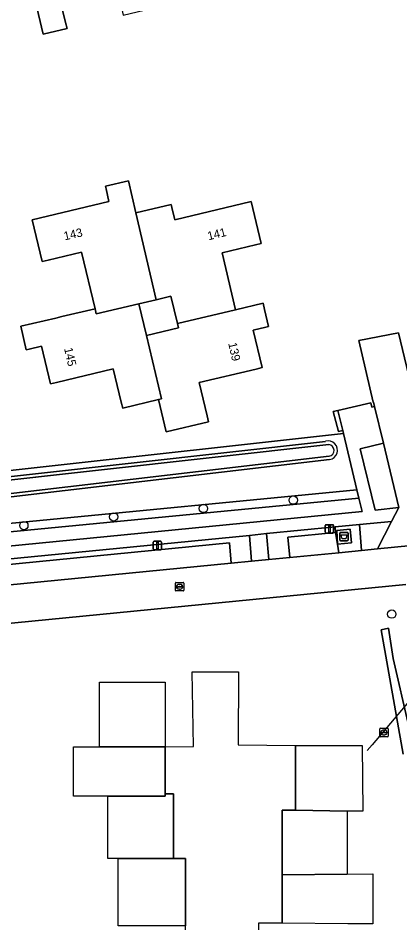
# Model space of a CAD drawing. Extents: x 156661 to 157576, y 383570 to 384425.
# Drawn here: x 156914.8 to 156959.7, y 383880.2 to 383986.9 of the extents above; entities that cross this region are included whole.
import ezdxf

# ---------------------------------------------------------------- set-up
doc = ezdxf.new("R2010")
doc.units = 0
for name, color, linetype in [('IMGEO_Afval_apart_plaats', 7, 'Continuous'), ('IMGEO_Berm_groen', 7, 'Continuous'), ('IMGEO_Boom', 7, 'Continuous'), ('IMGEO_Duiker', 7, 'Continuous'), ('IMGEO_Erf', 7, 'Continuous'), ('IMGEO_Groenvoorziening', 7, 'Continuous'), ('IMGEO_Haag', 7, 'Continuous'), ('IMGEO_Hek', 7, 'Continuous'), ('IMGEO_Lichtmast', 7, 'Continuous'), ('IMGEO_Meer_plas_ven_vijver', 7, 'Continuous'), ('IMGEO_Muur', 7, 'Continuous'), ('IMGEO_Oever', 7, 'Continuous'), ('IMGEO_Pand', 7, 'Continuous'), ('IMGEO_Pand_nummerreeks', 7, 'Continuous'), ('IMGEO_Pand_vergunning_verleend', 7, 'Continuous'), ('IMGEO_Parkeervlak_open', 7, 'Continuous'), ('IMGEO_Rijbaan_lokaal_open', 7, 'Continuous'), ('IMGEO_Rioolput', 7, 'Continuous'), ('IMGEO_Verkeerseiland_groen', 7, 'Continuous'), ('IMGEO_Voetpad_gesloten', 7, 'Continuous'), ('IMGEO_Voetpad_op_trap', 7, 'Continuous'), ('IMGEO_Voetpad_open', 7, 'Continuous'), ('IMGEO_Waterloop', 7, 'Continuous')]:
    doc.layers.add(name, color=color, linetype=linetype)

msp = doc.modelspace()

# ---------------------------------------------------------------- linework, layer by layer
at = {"layer": 'IMGEO_Afval_apart_plaats'}
for p, q in [((156952.64, 383925.35), (156952.64, 383926.15)), ((156952.64, 383926.15), (156952.64, 383925.35)), ((156952.74, 383926.25), (156953.53, 383926.25)), ((156953.53, 383926.25), (156952.74, 383926.25)), ((156953.63, 383926.15), (156953.63, 383925.35)), ((156953.63, 383925.35), (156953.63, 383926.15)), ((156953.53, 383925.25), (156952.74, 383925.25)), ((156952.74, 383925.25), (156953.53, 383925.25))]:
    msp.add_line(p, q, dxfattribs=at)
msp.add_lwpolyline([(156952.79, 383925.96), (156953.49, 383925.96), (156953.34, 383925.49), (156952.94, 383925.49), (156952.79, 383925.96)], dxfattribs=at)
for centre, start, end in [((156952.74, 383926.15), 90, 180), ((156952.74, 383926.15), 90, 180), ((156953.53, 383926.15), 0, 90), ((156953.53, 383926.15), 360, 90), ((156952.74, 383925.35), 180, 270), ((156952.74, 383925.35), 180, 270), ((156953.53, 383925.35), 270, 0), ((156953.53, 383925.35), 270, 0)]:
    msp.add_arc(centre, 0.1, start, end, dxfattribs=at)
at = {"layer": 'IMGEO_Berm_groen'}
msp.add_lwpolyline([(156853.8, 383916.58), (156939.65, 383925.02), (156939.88, 383922.62), (156942.26, 383922.86), (156942.03, 383925.89), (156868.5, 383918.71), (156853.28, 383917.32)], dxfattribs=at)
at = {"layer": 'IMGEO_Boom'}
for centre in [(156947.17, 383930.06), (156936.6, 383929.07), (156926.03, 383928.08), (156915.46, 383927.06), (156958.76, 383916.62)]:
    msp.add_circle(centre, 0.489, dxfattribs=at)
at = {"layer": 'IMGEO_Duiker'}
msp.add_lwpolyline([(156965.05, 383911.36), (156964.87, 383911.15), (156956.47, 383901.23), (156955.88, 383900.53)], dxfattribs=at)
at = {"layer": 'IMGEO_Erf'}
for points in [[(156971.91, 384032.86), (156863.46, 384006.69), (156882.01, 383929.99), (156953.1, 383937.9), (156953.01, 383938.27), (156952.49, 383938.15), (156951.88, 383940.49), (156952.41, 383940.6), (156956.3, 383941.53), (156956.43, 383941), (156956.74, 383941.08), (156956.61, 383941.61), (156956.56, 383941.6), (156954.88, 383948.87), (156959.57, 383949.78), (156961.26, 383942.72)], [(156919.43, 383990.23), (156920.36, 383986.35), (156920.54, 383985.62), (156917.75, 383984.95), (156916.82, 383988.76)]]:
    msp.add_lwpolyline(points, dxfattribs=at)
for points in [[(156932.79, 383964.88), (156932.87, 383964.54), (156933.22, 383963.07), (156942.23, 383965.23), (156943.41, 383960.29), (156942.71, 383960.12), (156938.79, 383959.19), (156940.37, 383952.49), (156943.61, 383953.26), (156943.79, 383952.52), (156944.27, 383950.51), (156943.93, 383950.43), (156942.46, 383950.08), (156943.51, 383945.67), (156942.8, 383945.5), (156936.11, 383943.91), (156937.04, 383939.99), (156937.21, 383939.28), (156932.22, 383938.09), (156931.32, 383941.9), (156927.1, 383940.9), (156926.93, 383941.59), (156925.97, 383945.52), (156919.29, 383943.92), (156918.58, 383943.75), (156917.55, 383948.21), (156916.1, 383947.86), (156915.75, 383947.78), (156915.1, 383950.55), (156919.21, 383951.51), (156919.94, 383951.68), (156923.85, 383952.6), (156922.24, 383959.27), (156918.34, 383958.35), (156917.61, 383958.18), (156916.44, 383963.09), (156925.47, 383965.24), (156925.14, 383966.72), (156925.06, 383967.06), (156927.77, 383967.69), (156928.65, 383963.9)], [(156933.65, 383950.35), (156933.53, 383950.86), (156932.77, 383954.08), (156931.04, 383953.67), (156929, 383953.19), (156929.88, 383949.46)]]:
    msp.add_lwpolyline(points, close=True, dxfattribs=at)
at = {"layer": 'IMGEO_Groenvoorziening'}
for points in [[(156971.83, 384035.57), (156971.46, 384036.85), (156855.45, 384008.78), (156857.54, 383999.9), (156875.12, 383923.56), (156954.67, 383931.28), (156953.1, 383937.9)], [(156953.1, 383937.9), (156882.01, 383929.99), (156863.46, 384006.69), (156971.91, 384032.86), (156984.85, 383993.38), (157001.3, 383943.16), (156963.71, 383939.04), (156964.42, 383936.12), (156965.67, 383936.39)], [(156882.29, 383929.29), (156950.98, 383936.98)], [(156951.45, 383934.84), (156882.83, 383926.78)], [(156960.43, 383920.1), (156912.35, 383915.39), (156904.42, 383914.61), (156868, 383911.04), (156868.44, 383907.02), (156862.51, 383906.39)], [(156960.12, 383900.1), (156957.52, 383914.75), (156958.36, 383914.95), (156958.91, 383911.41), (156960.79, 383903.39), (156961.58, 383900.3)]]:
    msp.add_lwpolyline(points, dxfattribs=at)
for points in [[(156954.9, 383930.3), (156954.67, 383931.28), (156875.12, 383923.56), (156857.54, 383999.9), (156855.45, 384008.78), (156854.96, 384008.66), (156854.48, 384008.54), (156856.57, 383999.67), (156874.23, 383922.97), (156874.34, 383922.48), (156874.83, 383922.53)], [(156957.78, 383936.78), (156955.06, 383936.1), (156956.8, 383928.86), (156959.6, 383929.2)], [(156875.22, 383920.86), (156955.27, 383928.7), (156954.9, 383930.3), (156874.83, 383922.53)], [(156946.77, 383923.3), (156946.52, 383925.7), (156952.13, 383926.24), (156952.09, 383926.89), (156944.03, 383926.11), (156944.3, 383923.06)]]:
    msp.add_lwpolyline(points, close=True, dxfattribs=at)
msp.add_arc((156951.28, 383935.93), 1.1, 278.5005, 105.9803, dxfattribs=at)
at = {"layer": 'IMGEO_Haag'}
msp.add_lwpolyline([(156857.54, 383999.9), (156855.45, 384008.78), (156854.96, 384008.66), (156854.48, 384008.54), (156856.57, 383999.67), (156874.23, 383922.97), (156874.34, 383922.48), (156874.83, 383922.53), (156954.9, 383930.3), (156954.67, 383931.28), (156875.12, 383923.56)], close=True, dxfattribs=at)
at = {"layer": 'IMGEO_Hek'}
msp.add_lwpolyline([(156953.1, 383937.9), (156882.01, 383929.99), (156863.46, 384006.69), (156971.91, 384032.86), (156984.85, 383993.38), (157001.3, 383943.16)], dxfattribs=at)
at = {"layer": 'IMGEO_Lichtmast'}
for p, q in [((156951.03, 383927.16), (156951.82, 383927.16)), ((156951.82, 383927.16), (156951.03, 383927.16)), ((156950.93, 383926.26), (156950.93, 383927.06)), ((156950.93, 383927.06), (156950.93, 383926.26)), ((156951.82, 383926.16), (156951.03, 383926.16)), ((156951.03, 383926.16), (156951.82, 383926.16)), ((156951.92, 383927.06), (156951.92, 383926.26)), ((156951.92, 383926.26), (156951.92, 383927.06)), ((156930.68, 383924.3), (156930.68, 383925.1)), ((156930.68, 383925.1), (156930.68, 383924.3)), ((156930.78, 383925.2), (156931.57, 383925.2)), ((156931.57, 383925.2), (156930.78, 383925.2)), ((156931.67, 383925.1), (156931.67, 383924.3)), ((156931.67, 383924.3), (156931.67, 383925.1)), ((156931.57, 383924.2), (156930.78, 383924.2)), ((156930.78, 383924.2), (156931.57, 383924.2))]:
    msp.add_line(p, q, dxfattribs=at)
for points in [[(156951.35, 383927.03), (156951.5, 383927.03), (156951.5, 383926.28), (156951.35, 383926.28), (156951.35, 383927.03)], [(156931.1, 383925.08), (156931.25, 383925.08), (156931.25, 383924.33), (156931.1, 383924.33), (156931.1, 383925.08)]]:
    msp.add_lwpolyline(points, dxfattribs=at)
for centre, start, end in [((156951.03, 383927.06), 90, 180), ((156951.03, 383927.06), 90, 180), ((156951.82, 383927.06), 0, 90), ((156951.82, 383927.06), 360, 90), ((156951.03, 383926.26), 180, 270), ((156951.03, 383926.26), 180, 270), ((156951.82, 383926.26), 270, 0), ((156951.82, 383926.26), 270, 0), ((156930.78, 383925.1), 90, 180), ((156930.78, 383925.1), 90, 180), ((156931.57, 383925.1), 0, 90), ((156931.57, 383925.1), 360, 90), ((156930.78, 383924.3), 180, 270), ((156930.78, 383924.3), 180, 270), ((156931.57, 383924.3), 270, 0), ((156931.57, 383924.3), 270, 0)]:
    msp.add_arc(centre, 0.1, start, end, dxfattribs=at)
at = {"layer": 'IMGEO_Meer_plas_ven_vijver'}
msp.add_lwpolyline([(156961.58, 383900.3), (156960.79, 383903.39), (156958.91, 383911.41), (156958.36, 383914.95), (156957.52, 383914.75), (156960.12, 383900.1)], dxfattribs=at)
at = {"layer": 'IMGEO_Muur'}
msp.add_lwpolyline([(156956.74, 383941.08), (156956.43, 383941)], dxfattribs=at)
msp.add_lwpolyline([(156952.41, 383940.6), (156951.88, 383940.49), (156952.49, 383938.15), (156953.01, 383938.27)], close=True, dxfattribs=at)
at = {"layer": 'IMGEO_Oever'}
for points in [[(156950.98, 383936.98), (156882.29, 383929.29)], [(156882.3, 383928.89), (156951.36, 383936.62)], [(156951.39, 383935.24), (156882.8, 383927.19)], [(156882.83, 383926.78), (156951.45, 383934.84)]]:
    msp.add_lwpolyline(points, dxfattribs=at)
for centre, radius, start, end in [((156951.28, 383935.93), 1.1, 278.5005, 105.9803), ((156951.28, 383935.92), 0.695, 278.961, 83.5333)]:
    msp.add_arc(centre, radius, start, end, dxfattribs=at)
at = {"layer": 'IMGEO_Pand'}
for points in [[(156918.61, 383997.62), (156918.71, 383997.15), (156914.95, 383996.26), (156916.82, 383988.76), (156917.75, 383984.95), (156920.54, 383985.62), (156920.36, 383986.35), (156919.43, 383990.23), (156926.08, 383991.83), (156926.98, 383987.92), (156927.14, 383987.19), (156932.11, 383988.39), (156929.97, 383997.4), (156931.44, 383997.77), (156931.78, 383997.86), (156931.11, 384000.62), (156930.46, 384000.47), (156929.73, 384000.29), (156925.52, 383999.26)], [(156928.65, 383963.9), (156927.77, 383967.69), (156925.06, 383967.06), (156925.14, 383966.72), (156925.47, 383965.24), (156916.44, 383963.09), (156917.61, 383958.18), (156918.34, 383958.35), (156922.24, 383959.27), (156923.85, 383952.6), (156923.99, 383952.02), (156929, 383953.19), (156931.04, 383953.67)], [(156940.37, 383952.49), (156938.79, 383959.19), (156942.71, 383960.12), (156943.41, 383960.29), (156942.23, 383965.23), (156933.22, 383963.07), (156932.87, 383964.54), (156932.79, 383964.88), (156928.65, 383963.9), (156931.04, 383953.67), (156932.77, 383954.08), (156933.53, 383950.86)], [(156931.32, 383941.9), (156931.66, 383941.98), (156929.88, 383949.46), (156929, 383953.19), (156923.99, 383952.02), (156923.85, 383952.6), (156919.94, 383951.68), (156919.21, 383951.51), (156915.1, 383950.55), (156915.75, 383947.78), (156916.1, 383947.86), (156917.55, 383948.21), (156918.58, 383943.75), (156919.29, 383943.92), (156925.97, 383945.52), (156926.93, 383941.59), (156927.1, 383940.9)], [(156940.37, 383952.49), (156933.53, 383950.86), (156933.65, 383950.35), (156929.88, 383949.46), (156931.66, 383941.98), (156931.32, 383941.9), (156932.22, 383938.09), (156937.21, 383939.28), (156937.04, 383939.99), (156936.11, 383943.91), (156942.8, 383945.5), (156943.51, 383945.67), (156942.46, 383950.08), (156943.93, 383950.43), (156944.27, 383950.51), (156943.79, 383952.52), (156943.61, 383953.26)]]:
    msp.add_lwpolyline(points, close=True, dxfattribs=at)
at = {"layer": 'IMGEO_Pand_vergunning_verleend'}
for points in [[(156947.44, 383901.14), (156947.44, 383893.51), (156945.85, 383893.51), (156945.85, 383885.88), (156945.85, 383880.19), (156943.07, 383880.19), (156943.07, 383874.28), (156934.5, 383874.28), (156934.5, 383879.89), (156934.5, 383887.82), (156933.08, 383887.82), (156933.08, 383895.45), (156932.09, 383895.45), (156932.09, 383901), (156935.41, 383901.03), (156935.26, 383909.8), (156940.71, 383909.8), (156940.68, 383901.21)], [(156932.09, 383908.59), (156932.09, 383901), (156924.36, 383901), (156924.36, 383908.59)], [(156924.36, 383901), (156932.09, 383901), (156932.09, 383895.45), (156932.08, 383895.15), (156925.35, 383895.15), (156921.32, 383895.15), (156921.32, 383901)], [(156953.53, 383893.41), (156947.44, 383893.51), (156947.44, 383901.14), (156955.26, 383901.14), (156955.35, 383893.41)], [(156925.35, 383895.15), (156932.08, 383895.15), (156932.09, 383895.45), (156933.08, 383895.45), (156933.08, 383887.82), (156926.57, 383887.82), (156925.35, 383887.82)], [(156953.53, 383885.97), (156945.85, 383885.88), (156945.85, 383893.51), (156947.44, 383893.51), (156953.53, 383893.41)], [(156926.57, 383887.82), (156933.08, 383887.82), (156934.5, 383887.82), (156934.5, 383879.89), (156926.57, 383879.89)], [(156945.85, 383880.19), (156945.85, 383885.88), (156953.53, 383885.97), (156956.55, 383886), (156956.55, 383880.13), (156953.58, 383880.13)]]:
    msp.add_lwpolyline(points, close=True, dxfattribs=at)
at = {"layer": 'IMGEO_Parkeervlak_open'}
msp.add_lwpolyline([(156952.53, 383923.86), (156952.36, 383924.88), (156952.13, 383926.24), (156946.52, 383925.7), (156946.77, 383923.3)], close=True, dxfattribs=at)
msp.add_lwpolyline([(156855.1, 383914.32), (156858.63, 383914.67), (156939.88, 383922.62), (156939.65, 383925.02), (156853.8, 383916.58)], dxfattribs=at)
at = {"layer": 'IMGEO_Rijbaan_lokaal_open'}
msp.add_lwpolyline([(156963.71, 383939.04), (156963.66, 383939.23), (156962.75, 383943.05), (156961.58, 383942.81), (156961.7, 383942.27), (156961.38, 383942.2), (156961.26, 383942.72), (156959.57, 383949.78), (156954.88, 383948.87), (156956.56, 383941.6), (156956.61, 383941.61), (156956.74, 383941.08), (156957.78, 383936.78), (156959.6, 383929.2), (156958.75, 383927.53), (156957.07, 383924.31), (156970.29, 383925.6), (156967.79, 383928.41), (156966.54, 383929.79), (156965.74, 383930.72), (156964.42, 383936.12)], close=True, dxfattribs=at)
msp.add_lwpolyline([(156970.29, 383925.6), (156957.07, 383924.31), (156955.2, 383924.12), (156952.53, 383923.86), (156946.77, 383923.3), (156944.3, 383923.06), (156942.26, 383922.86), (156939.88, 383922.62), (156858.63, 383914.67), (156859, 383910.16), (156866.03, 383910.84), (156868, 383911.04), (156904.42, 383914.61), (156912.35, 383915.39), (156960.43, 383920.1)], dxfattribs=at)
at = {"layer": 'IMGEO_Rioolput'}
for p, q in [((156933.29, 383919.42), (156933.29, 383920.28)), ((156933.36, 383920.35), (156934.22, 383920.35)), ((156933.55, 383919.84), (156933.55, 383919.86)), ((156933.59, 383919.89), (156933.99, 383919.89)), ((156933.99, 383919.81), (156933.59, 383919.81)), ((156933.78, 383920.13), (156933.8, 383920.13)), ((156934.03, 383919.86), (156934.03, 383919.84)), ((156934.29, 383920.28), (156934.29, 383919.42)), ((156934.22, 383919.35), (156933.36, 383919.35)), ((156933.8, 383919.57), (156933.77, 383919.57)), ((156957.34, 383902.24), (156957.34, 383903.09)), ((156957.42, 383903.17), (156958.27, 383903.17)), ((156957.6, 383902.66), (156957.6, 383902.67)), ((156957.64, 383902.71), (156958.04, 383902.71)), ((156958.04, 383902.62), (156957.64, 383902.62)), ((156957.83, 383902.95), (156957.86, 383902.95)), ((156958.09, 383902.67), (156958.09, 383902.66)), ((156958.34, 383903.09), (156958.34, 383902.24)), ((156958.27, 383902.17), (156957.42, 383902.17)), ((156957.85, 383902.39), (156957.83, 383902.39))]:
    msp.add_line(p, q, dxfattribs=at)
for points in [[(156933.29, 383919.42), (156933.29, 383920.28)], [(156933.36, 383920.35), (156934.22, 383920.35)], [(156934.29, 383920.28), (156934.29, 383919.42)], [(156934.22, 383919.35), (156933.36, 383919.35)], [(156957.34, 383902.24), (156957.34, 383903.09)], [(156957.42, 383903.17), (156958.27, 383903.17)], [(156958.34, 383903.09), (156958.34, 383902.24)], [(156958.27, 383902.17), (156957.42, 383902.17)]]:
    msp.add_lwpolyline(points, dxfattribs=at)
for centre, radius, start, end in [((156933.37, 383920.28), 0.0765, 91.552, 178.448), ((156933.37, 383920.28), 0.0765, 91.552, 178.448), ((156933.59, 383919.85), 0.0403, 85.8775, 175.7526), ((156933.58, 383919.84), 0.0366, 178.938, 274.7102), ((156933.99, 383919.86), 0.0386, 1.7309, 96.639), ((156933.99, 383919.85), 0.043, 264.8664, 352.4533), ((156934.21, 383920.28), 0.0765, 1.552, 88.448), ((156934.21, 383920.28), 0.0765, 1.552, 88.448), ((156933.37, 383919.43), 0.0765, 181.552, 268.448), ((156933.37, 383919.43), 0.0765, 181.552, 268.448), ((156934.21, 383919.43), 0.0765, 271.552, 358.448), ((156934.21, 383919.43), 0.0765, 271.552, 358.448), ((156957.42, 383903.09), 0.0765, 91.552, 178.448), ((156957.42, 383903.09), 0.0765, 91.552, 178.448), ((156957.64, 383902.67), 0.0403, 85.8775, 175.7526), ((156957.64, 383902.66), 0.0366, 178.938, 274.7102), ((156958.05, 383902.67), 0.0386, 1.7309, 96.639), ((156958.04, 383902.67), 0.043, 264.8664, 352.4533), ((156958.27, 383903.09), 0.0765, 1.552, 88.448), ((156958.27, 383903.09), 0.0765, 1.552, 88.448), ((156957.42, 383902.24), 0.0765, 181.552, 268.448), ((156957.42, 383902.24), 0.0765, 181.552, 268.448), ((156958.27, 383902.24), 0.0765, 271.552, 358.448), ((156958.27, 383902.24), 0.0765, 271.552, 358.448)]:
    msp.add_arc(centre, radius, start, end, dxfattribs=at)
for centre, major_axis, ratio, start_param, end_param in [((156933.78, 383919.85), (-0.387, 0.002), 0.722429, 4.712389, 7.853982), ((156933.8, 383919.85), (-0.39, 0.002), 0.717154, 1.570796, 4.712389), ((156957.83, 383902.67), (-0.387, 0.002), 0.722429, 4.712389, 7.853982), ((156957.85, 383902.67), (-0.39, 0.002), 0.717154, 1.570796, 4.712389)]:
    msp.add_ellipse(centre, major_axis=major_axis, ratio=ratio, start_param=start_param, end_param=end_param, dxfattribs=at)
at = {"layer": 'IMGEO_Verkeerseiland_groen'}
msp.add_lwpolyline([(156958.75, 383927.53), (156954.95, 383927.18), (156955.2, 383924.12), (156957.07, 383924.31)], close=True, dxfattribs=at)
at = {"layer": 'IMGEO_Voetpad_gesloten'}
msp.add_lwpolyline([(156953.87, 383926.64), (156952.3, 383926.49), (156952.36, 383924.88), (156954.02, 383925.03)], close=True, dxfattribs=at)
at = {"layer": 'IMGEO_Voetpad_op_trap'}
msp.add_lwpolyline([(156944.03, 383926.11), (156942.03, 383925.89), (156942.26, 383922.86), (156944.3, 383923.06)], close=True, dxfattribs=at)
at = {"layer": 'IMGEO_Voetpad_open'}
for points in [[(156955.06, 383936.1), (156957.78, 383936.78), (156956.74, 383941.08), (156956.43, 383941), (156956.3, 383941.53), (156952.41, 383940.6), (156953.01, 383938.27), (156953.1, 383937.9), (156954.67, 383931.28), (156954.9, 383930.3), (156955.27, 383928.7), (156875.22, 383920.86), (156870.13, 383920.36), (156867.98, 383920.71), (156860.16, 383919.98), (156854.49, 383919.45), (156853.18, 383919.27)], [(156853.28, 383917.32), (156868.5, 383918.71), (156942.03, 383925.89), (156944.03, 383926.11), (156952.09, 383926.89), (156954.95, 383927.18), (156958.75, 383927.53), (156959.6, 383929.2), (156956.8, 383928.86), (156955.06, 383936.1)]]:
    msp.add_lwpolyline(points, dxfattribs=at)
for points in [[(156954.95, 383927.18), (156952.09, 383926.89), (156952.13, 383926.24), (156952.36, 383924.88), (156952.53, 383923.86), (156955.2, 383924.12)], [(156952.36, 383924.88), (156952.3, 383926.49), (156953.87, 383926.64), (156954.02, 383925.03)]]:
    msp.add_lwpolyline(points, close=True, dxfattribs=at)
at = {"layer": 'IMGEO_Waterloop'}
for points in [[(156951.36, 383936.62), (156882.3, 383928.89)], [(156882.8, 383927.19), (156951.39, 383935.24)]]:
    msp.add_lwpolyline(points, dxfattribs=at)
msp.add_arc((156951.28, 383935.92), 0.695, 278.961, 83.5333, dxfattribs=at)

# ---------------------------------------------------------------- texts
at = {"layer": 'IMGEO_Pand_nummerreeks'}
for s, rotation, p in [('143', 12.8376, (156920.27, 383960.66)), ('141', 13.6762, (156937.2, 383960.67)), ('139', 282.761, (156939.51, 383948.53)), ('145', 282.9567, (156920.19, 383947.92))]:
    msp.add_text(s, height=1, rotation=rotation, dxfattribs=at).set_placement(p)

doc.saveas('drawing.dxf')
